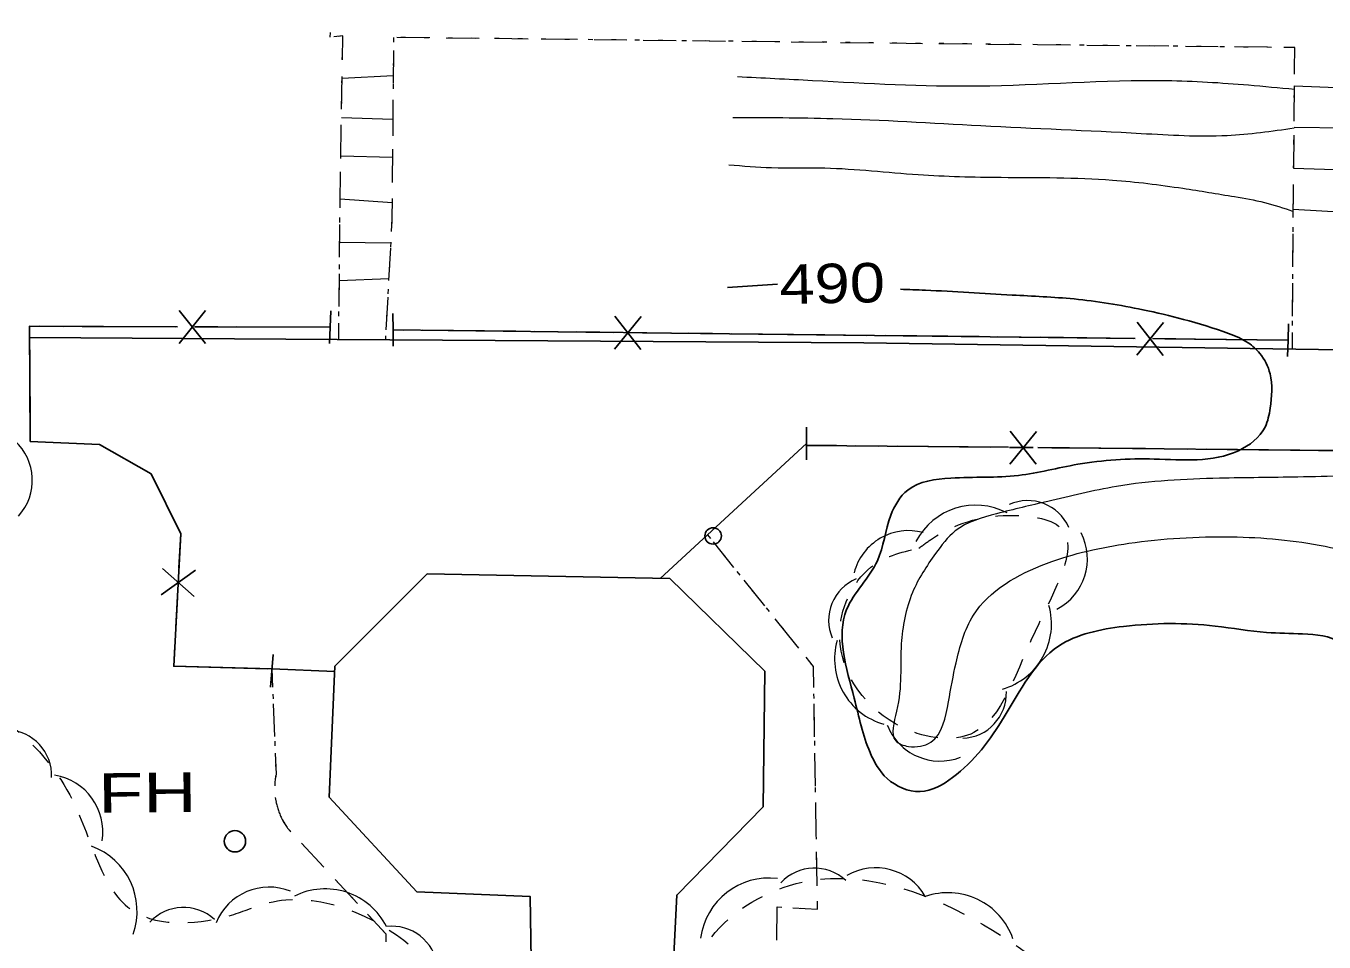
# Model space of a CAD drawing. Extents: x 2362213 to 2366494, y 6968794 to 6978110.
# Drawn here: x 2363996.3 to 2364154.4, y 6972258.7 to 6972370.1 of the extents above; entities that cross this region are included whole.
import ezdxf
from ezdxf.enums import TextEntityAlignment as Align

# ---------------------------------------------------------------- set-up
doc = ezdxf.new("R2010")
doc.units = 0
doc.header["$LTSCALE"] = 1.9
for name, pattern in [('DOTTED', [1.5, 0.3, -1.2]), ('LONG_DASH_SHORT_DASH', [9.9, 6, -1.2, 1.5, -1.2]), ('SHORT_DASHED', [2.7, 1.5, -1.2])]:
    doc.linetypes.add(name, pattern=pattern)
for name, color, linetype, lineweight in [('11', 7, 'Continuous', 25), ('13', 7, 'Continuous', 13), ('17', 7, 'Continuous', 25), ('2', 7, 'Continuous', 25), ('20', 7, 'Continuous', 25), ('29', 7, 'Continuous', 13), ('31', 7, 'Continuous', 25), ('35', 7, 'Continuous', 13), ('9', 7, 'Continuous', 13)]:
    doc.layers.add(name, color=color, linetype=linetype, lineweight=lineweight)

msp = doc.modelspace()

# ---------------------------------------------------------------- linework, layer by layer
at = {"layer": '11'}
msp.add_lwpolyline([(2364091.407, 6972317.335), (2364091.408, 6972319.335), (2364091.409, 6972321.335)], dxfattribs=at)
msp.add_lwpolyline([(2364074.764, 6972302.896), (2364045.218, 6972303.454), (2364033.944, 6972292.236), (2364033.275, 6972276.309), (2364043.956, 6972264.77), (2364057.762, 6972264.192), (2364057.979, 6972248.753), (2364046.682, 6972237.915), (2364046.542, 6972222.143), (2364057.564, 6972210.417), (2364087.81, 6972209.945), (2364099.265, 6972221.125), (2364099.234, 6972237.005), (2364087.978, 6972248.949), (2364074.817, 6972249.053), (2364075.601, 6972264.382), (2364086.129, 6972275.142), (2364086.302, 6972291.645)], close=True, dxfattribs=at)
at = {"layer": '13'}
for p, q in [((2364045.516, 6972368.681), (2364041.516, 6972368.733)), ((2364051.517, 6972368.618), (2364047.517, 6972368.66)), ((2364057.518, 6972368.545), (2364053.517, 6972368.597)), ((2364063.519, 6972368.472), (2364059.519, 6972368.524)), ((2364069.52, 6972368.399), (2364065.52, 6972368.451)), ((2364075.521, 6972368.337), (2364071.52, 6972368.379)), ((2364081.522, 6972368.264), (2364077.521, 6972368.316)), ((2364087.523, 6972368.191), (2364083.522, 6972368.243)), ((2364093.524, 6972368.118), (2364089.523, 6972368.17)), ((2364099.526, 6972368.055), (2364095.524, 6972368.097)), ((2364105.526, 6972367.982), (2364101.525, 6972368.034)), ((2364041.091, 6972367.149), (2364041.059, 6972363.147)), ((2364111.527, 6972367.919), (2364107.526, 6972367.961)), ((2364117.528, 6972367.857), (2364113.527, 6972367.898)), ((2364123.528, 6972367.794), (2364119.528, 6972367.836)), ((2364129.529, 6972367.731), (2364125.529, 6972367.773)), ((2364135.53, 6972367.668), (2364131.53, 6972367.71)), ((2364141.531, 6972367.605), (2364137.53, 6972367.647)), ((2364147.532, 6972367.542), (2364143.532, 6972367.584)), ((2364034.779, 6972359.997), (2364034.841, 6972363.998)), ((2364150.785, 6972358.832), (2364150.817, 6972362.832)), ((2364041.038, 6972361.147), (2364041.006, 6972357.146)), ((2364034.686, 6972353.996), (2364034.748, 6972357.997)), ((2364150.722, 6972352.831), (2364150.764, 6972356.832)), ((2364040.985, 6972355.146), (2364040.953, 6972351.146)), ((2364034.53, 6972341.994), (2364034.572, 6972345.996)), ((2364150.626, 6972340.83), (2364150.658, 6972344.831)), ((2364040.719, 6972343.143), (2364040.507, 6972339.151)), ((2364034.467, 6972335.993), (2364034.509, 6972339.994)), ((2364150.584, 6972334.829), (2364150.615, 6972338.829)), ((2364040.396, 6972337.15), (2364040.184, 6972333.158)), ((2364034.425, 6972331.993), (2364034.446, 6972333.993)), ((2364150.562, 6972330.828), (2364150.573, 6972332.829)), ((2364082.562, 6972304.24), (2364080.062, 6972307.356)), ((2364086.326, 6972299.565), (2364083.817, 6972302.683)), ((2364090.091, 6972294.891), (2364087.581, 6972298.007)), ((2364026.289, 6972291.663), (2364026.368, 6972289.664)), ((2364026.447, 6972287.665), (2364026.615, 6972283.666)), ((2364092.388, 6972283.652), (2364092.32, 6972287.652)), ((2364092.495, 6972277.653), (2364092.427, 6972281.653)), ((2364092.592, 6972271.654), (2364092.524, 6972275.653)), ((2364029.909, 6972270.687), (2364032.637, 6972267.763)), ((2364092.69, 6972265.654), (2364092.622, 6972269.654)), ((2364034.001, 6972266.296), (2364036.729, 6972263.361)), ((2364087.794, 6972258.898), (2364087.806, 6972262.898))]:
    msp.add_line(p, q, dxfattribs=at)
at = {"layer": '13', "linetype": 'DOTTED'}
msp.add_line((2364026.289, 6972291.663), (2364026.799, 6972279.079), dxfattribs=at)
for points in [[(2364034.425, 6972331.993), (2364034.604, 6972348.976), (2364034.914, 6972368.92), (2364033.405, 6972368.776), (2364033.721, 6972377.548)], [(2364150.562, 6972330.828), (2364150.689, 6972350.022), (2364150.862, 6972367.504), (2364041.106, 6972368.739), (2364040.916, 6972346.666), (2364040.116, 6972331.957)], [(2364104.942, 6972207.718), (2364100.511, 6972213.097), (2364104.463, 6972217.084), (2364106.348, 6972220.702), (2364106.73, 6972236.257), (2364104.796, 6972241.909), (2364087.792, 6972253.867), (2364087.805, 6972262.958), (2364092.738, 6972262.655), (2364092.247, 6972292.211), (2364079.354, 6972308.239)], [(2364028.211, 6972272.511), (2364040.164, 6972259.664), (2364039.65, 6972226.528)]]:
    msp.add_lwpolyline(points, dxfattribs=at)
at = {"layer": '13'}
for points in [[(2364034.871, 6972365.998), (2364034.914, 6972368.92), (2364033.835, 6972368.82)], [(2364150.838, 6972364.833), (2364150.862, 6972367.504), (2364149.532, 6972367.521)], [(2364034.593, 6972347.996), (2364034.604, 6972348.976), (2364034.655, 6972351.996)], [(2364150.669, 6972346.831), (2364150.689, 6972350.022), (2364150.701, 6972350.832)], [(2364040.932, 6972349.146), (2364040.916, 6972346.666), (2364040.83, 6972345.145)], [(2364092.291, 6972289.652), (2364092.247, 6972292.211), (2364091.346, 6972293.333)], [(2364026.694, 6972281.667), (2364026.799, 6972279.079), (2364026.77, 6972278.938), (2364026.741, 6972278.798), (2364026.723, 6972278.648), (2364026.704, 6972278.508), (2364026.686, 6972278.367), (2364026.667, 6972278.216), (2364026.648, 6972278.076), (2364026.64, 6972277.936), (2364026.631, 6972277.786), (2364026.632, 6972277.686)], [(2364026.791, 6972275.697), (2364026.812, 6972275.628), (2364026.843, 6972275.488), (2364026.884, 6972275.348), (2364026.916, 6972275.209), (2364026.957, 6972275.069), (2364026.998, 6972274.929), (2364027.04, 6972274.79), (2364027.091, 6972274.66), (2364027.132, 6972274.521), (2364027.184, 6972274.381), (2364027.245, 6972274.252), (2364027.296, 6972274.112), (2364027.357, 6972273.983), (2364027.419, 6972273.853), (2364027.48, 6972273.724), (2364027.541, 6972273.594), (2364027.612, 6972273.465), (2364027.684, 6972273.336), (2364027.755, 6972273.216), (2364027.826, 6972273.087), (2364027.907, 6972272.968), (2364027.978, 6972272.839), (2364028.059, 6972272.719), (2364028.141, 6972272.6), (2364028.211, 6972272.511), (2364028.545, 6972272.154)], [(2364089.746, 6972262.836), (2364092.738, 6972262.655), (2364092.719, 6972263.655)], [(2364038.093, 6972261.894), (2364040.164, 6972259.664), (2364040.153, 6972258.704)]]:
    msp.add_lwpolyline(points, dxfattribs=at)
at = {"layer": '13', "lineweight": 25}
msp.add_circle((2364080.025, 6972308.086), 1, dxfattribs=at)
at = {"layer": '13', "linetype": 'DOTTED'}
msp.add_arc((2364034.915, 6972277.388), 8.291, 168.24089, 216.03626, dxfattribs=at)
at = {"layer": '17'}
for p, q in [((2364018.201, 6972335.508), (2364014.989, 6972331.518)), ((2364015.001, 6972335.518), (2364018.189, 6972331.508)), ((2364033.391, 6972333.493), (2364018.39, 6972333.53)), ((2364071.27, 6972334.784), (2364068.028, 6972330.813)), ((2364068.07, 6972334.813), (2364071.218, 6972330.783)), ((2364134.86, 6972334.049), (2364131.618, 6972330.088)), ((2364131.67, 6972334.089), (2364134.818, 6972330.049)), ((2364067.839, 6972332.851), (2364041.045, 6972333.156)), ((2364131.438, 6972332.126), (2364071.439, 6972332.805)), ((2364150.041, 6972331.904), (2364135.039, 6972332.081)), ((2364119.406, 6972320.801), (2364116.163, 6972316.83)), ((2364116.205, 6972320.831), (2364119.364, 6972316.801)), ((2364115.974, 6972318.869), (2364091.411, 6972319.105)), ((2364179.573, 6972318.244), (2364119.574, 6972318.833)), ((2364012.82, 6972300.926), (2364016.982, 6972303.905)), ((2364012.99, 6972304.117), (2364016.812, 6972300.714))]:
    msp.add_line(p, q, dxfattribs=at)
at = {"layer": '17', "linetype": 'LONG_DASH_SHORT_DASH'}
msp.add_line((2364150.041, 6972331.904), (2364041.045, 6972333.156), dxfattribs=at)
for points in [[(2364033.391, 6972333.493), (2363996.758, 6972333.594), (2363996.862, 6972319.584), (2364005.316, 6972319.215), (2364011.58, 6972315.654), (2364015.19, 6972308.338), (2364014.333, 6972292.22), (2364026.307, 6972291.904)], [(2364211.497, 6972263.486), (2364211.989, 6972312.613), (2364189.085, 6972318.155), (2364091.411, 6972319.105)]]:
    msp.add_lwpolyline(points, dxfattribs=at)
at = {"layer": '17'}
for points in [[(2364014.79, 6972333.536), (2363996.758, 6972333.594), (2363996.862, 6972319.584), (2364005.316, 6972319.215), (2364011.58, 6972315.654), (2364015.19, 6972308.338), (2364014.969, 6972304.216)], [(2364014.783, 6972300.625), (2364014.333, 6972292.22), (2364026.307, 6972291.904)]]:
    msp.add_lwpolyline(points, dxfattribs=at)
at = {"layer": '2'}
for p, q in [((2364091.408, 6972319.335), (2364073.564, 6972302.915)), ((2364026.307, 6972291.904), (2364033.92, 6972291.576))]:
    msp.add_line(p, q, dxfattribs=at)
for points in [[(2364212.614, 6972335.16), (2364189.088, 6972330.415), (2364156.503, 6972330.745), (2364098.372, 6972331.592), (2364034.235, 6972331.991), (2363996.771, 6972332.244)], [(2364033.472, 6972335.494), (2364033.391, 6972333.493), (2364033.31, 6972331.492)], [(2364041.074, 6972331.156), (2364041.045, 6972333.156), (2364041.015, 6972335.156)], [(2364150.092, 6972333.904), (2364150.041, 6972331.904), (2364149.99, 6972329.903)], [(2364026.46, 6972293.655), (2364026.289, 6972291.663), (2364026.118, 6972289.672)]]:
    msp.add_lwpolyline(points, dxfattribs=at)
at = {"layer": '20'}
msp.add_circle((2364021.786, 6972270.93), 1.3, dxfattribs=at)
at = {"layer": '29'}
for centre, radius, start, end in [((2363990.621, 6972314.861), 6.496, 317.82148, 47.82148), ((2364112.012, 6972303.577), 8.248, 62.33333, 152.33333), ((2364118.32, 6972306.883), 5.495, 24.03678, 114.03678), ((2364103.839, 6972301.856), 6.876, 75.18483, 165.18483), ((2364118.727, 6972305.291), 6.876, 297.46231, 27.46231), ((2364099.589, 6972297.813), 5.495, 112.98541, 202.98541), ((2364112.982, 6972297.375), 8.248, 285.92314, 15.92314), ((2364103.059, 6972293.112), 8.248, 164.17223, 254.17223), ((2364110.248, 6972288.972), 5.495, 271.75033, 1.75033), ((2363993.904, 6972278.917), 5.569, 357.76049, 87.76049), ((2364107.638, 6972287.565), 6.876, 201.2658, 291.2658), ((2363998.735, 6972272.084), 6.969, 350.89891, 80.89891), ((2364001.515, 6972262.451), 8.359, 340.254, 70.254), ((2364092.362, 6972262.082), 5.582, 46.95733, 136.95733), ((2364099.821, 6972260.721), 6.984, 30.13221, 120.13221), ((2364025.945, 6972258.384), 6.969, 67.9202, 157.9202), ((2364086.814, 6972258.078), 8.377, 82.82142, 172.82142), ((2364032.788, 6972256.784), 8.359, 26.72281, 116.72281), ((2364108.623, 6972256.301), 8.377, 19.28758, 109.28758), ((2364015.534, 6972257.313), 5.569, 47.48666, 137.48666), ((2364040.928, 6972255.024), 5.569, 6.90129, 96.90129)]:
    msp.add_arc(centre, radius, start, end, dxfattribs=at)
at = {"layer": '29', "linetype": 'SHORT_DASHED'}
for points in [[(2364105.08, 6972306.604), (2364106.719, 6972307.76), (2364116.033, 6972310.589), (2364122.308, 6972309.118), (2364119.227, 6972296.459), (2364110.609, 6972283.706), (2364102.234, 6972285.226), (2364095.445, 6972296.612), (2364099.7, 6972304.623), (2364105.949, 6972306.743)], [(2364002.5, 6972032.034), (2363981.216, 6972031.281), (2363965.113, 6972033.558), (2363944.353, 6972058.733), (2363938.042, 6972103.955), (2363937.106, 6972153.928), (2363939.297, 6972178.99), (2363948.28, 6972195.626), (2363955.069, 6972199.951), (2363959.924, 6972225.708), (2363951.126, 6972253.846), (2363948.395, 6972267.54), (2363949.343, 6972293.971), (2363967.597, 6972294.775), (2363985.559, 6972290.335), (2364002.018, 6972275.921), (2364009.456, 6972262.422), (2364021.661, 6972262.038), (2364025.937, 6972263.469), (2364042.362, 6972258.885), (2364049.893, 6972249.316), (2364049.696, 6972227.003), (2364040.844, 6972210.288), (2364042.236, 6972190.211), (2364050.399, 6972166.826), (2364050.37, 6972138.336), (2364039.719, 6972118.392), (2364026.745, 6972108.349), (2364021.559, 6972100.549), (2364016.664, 6972074.761), (2364015.764, 6972053.761), (2364011.499, 6972039.551), (2364002.406, 6972032.463)], [(2364073.753, 6972229.492), (2364074.958, 6972240.484), (2364079.78, 6972259.201), (2364090.957, 6972265.968), (2364111.841, 6972261.407), (2364127.953, 6972249.69), (2364140.932, 6972237.293), (2364150.158, 6972217.769), (2364149.676, 6972192.814), (2364127.259, 6972175.53), (2364100.53, 6972178.585), (2364079.39, 6972180.474), (2364064.989, 6972186.857), (2364056.757, 6972205.86), (2364062.954, 6972218.879), (2364072.992, 6972229.555)]]:
    msp.add_spline(points, degree=3, dxfattribs=at)
at = {"layer": '31'}
msp.add_line((2364081.787, 6972338.314), (2364087.874, 6972338.712), dxfattribs=at)
msp.add_spline([(2364102.84, 6972338.094), (2364105.871, 6972337.983), (2364116.438, 6972337.394), (2364123.972, 6972336.916), (2364132.355, 6972335.605), (2364137.317, 6972334.433), (2364142.793, 6972332.715), (2364145.185, 6972331.577), (2364146.596, 6972330.301), (2364147.85, 6972327.813), (2364147.86, 6972323.633), (2364147.242, 6972321.326), (2364144, 6972318.455), (2364133.748, 6972317.438), (2364124.424, 6972316.799), (2364117.197, 6972315.45), (2364108.969, 6972315.122), (2364103.723, 6972313.652), (2364101.652, 6972310.602), (2364100.036, 6972305.066), (2364096.281, 6972299.12), (2364097.204, 6972288.348), (2364099.138, 6972281.727), (2364101.207, 6972278.577), (2364105.222, 6972276.994), (2364109.186, 6972278.683), (2364115.476, 6972286.092), (2364122.086, 6972294.676), (2364130.012, 6972297.071), (2364141.162, 6972297.117), (2364147.43, 6972296.347), (2364151.812, 6972296.169), (2364156.442, 6972295.083), (2364158.831, 6972292.125), (2364160.256, 6972289.459), (2364160.767, 6972284.074), (2364162.945, 6972279.085), (2364165.154, 6972269.865), (2364164.2, 6972261.715), (2364164.157, 6972253.674), (2364169.037, 6972243.28), (2364175.717, 6972237.964), (2364181.292, 6972235.407), (2364187.732, 6972229.158), (2364190.016, 6972223.559), (2364193.561, 6972213.603), (2364199.445, 6972206.788), (2364202.052, 6972198.673), (2364199.336, 6972190.977), (2364195.351, 6972186.188), (2364190.01, 6972183.197), (2364183.612, 6972181.786), (2364178.059, 6972182.144), (2364171.614, 6972185.782), (2364164.38, 6972189.343), (2364158.538, 6972190.548), (2364154.057, 6972191.705), (2364148.58, 6972192.373), (2364140.562, 6972192.107), (2364135.613, 6972191.95), (2364130.237, 6972192.549), (2364122.358, 6972191.474), (2364114.296, 6972188.446), (2364108.6, 6972185.882)], degree=3, dxfattribs=at)
at = {"layer": '35'}
for points in [[(2364150.811, 6972362.402), (2364145.217, 6972362.919), (2364135.24, 6972363.454), (2364112.265, 6972362.805), (2364092.128, 6972363.474), (2364082.983, 6972363.936)], [(2364082.44, 6972359.011), (2364094.622, 6972358.877), (2364112.631, 6972358.019), (2364132.161, 6972357.064), (2364142.604, 6972356.824), (2364150.766, 6972357.722)], [(2364156.982, 6972357.111), (2364163.014, 6972356.878), (2364167.565, 6972355.832), (2364175.992, 6972354.032), (2364185.051, 6972353.078), (2364190.675, 6972351.741), (2364195.111, 6972347.874), (2364197.12, 6972345.913), (2364199.868, 6972344.019), (2364201.142, 6972342.611), (2364203.512, 6972338.413), (2364205.18, 6972336.499), (2364205.619, 6972334.563), (2364205.944, 6972332.916), (2364206.745, 6972328.633), (2364207.416, 6972325.441), (2364207.944, 6972320.364), (2364208.244, 6972317.217), (2364207.15, 6972313.467), (2364204.179, 6972312.438), (2364196.566, 6972312.736), (2364187.127, 6972313.636), (2364174.486, 6972313.656), (2364168.381, 6972313.267), (2364166.166, 6972312.666), (2364165.388, 6972311.479), (2364166.158, 6972308.236), (2364171.608, 6972306.138), (2364177.776, 6972305.306), (2364186.266, 6972303.228), (2364191.265, 6972299.295), (2364194.967, 6972291.66), (2364192.618, 6972284.307), (2364186.443, 6972276.298), (2364184.488, 6972273.659), (2364183.127, 6972267.446), (2364183.072, 6972261.625), (2364185.262, 6972256.356), (2364190.813, 6972252.198), (2364194.778, 6972249.526), (2364200.631, 6972246.091), (2364205.045, 6972236.273), (2364207.432, 6972227.115), (2364209.143, 6972217.511), (2364210.284, 6972206.001), (2364210.991, 6972195.838), (2364210.178, 6972186.71), (2364206.661, 6972178.876), (2364200.562, 6972173.547), (2364193.549, 6972170.691), (2364188.918, 6972169.726), (2364182.15, 6972169.442), (2364173.736, 6972169.782), (2364167.01, 6972170.538), (2364157.223, 6972173.185), (2364150.176, 6972173.918), (2364138.499, 6972174.527), (2364132.401, 6972174.348), (2364126.267, 6972174.71)], [(2364081.925, 6972353.256), (2364087.139, 6972352.906), (2364093.619, 6972352.857), (2364105.007, 6972352.056), (2364115.091, 6972351.722), (2364128.665, 6972351.391), (2364137.225, 6972350.383), (2364143.526, 6972349.373), (2364147.152, 6972348.668), (2364150.672, 6972347.571)], [(2364156.995, 6972347.331), (2364160.667, 6972346.106), (2364162.586, 6972345.165), (2364166.25, 6972342.718), (2364169.314, 6972340.257), (2364171.614, 6972335.889), (2364175.471, 6972332.106), (2364177.736, 6972330.517), (2364178.425, 6972328.474), (2364178.831, 6972324.698), (2364178.516, 6972322.134), (2364174.454, 6972318.045), (2364169.799, 6972316.591), (2364162.666, 6972315.733), (2364151.22, 6972315.244), (2364141.671, 6972315.103), (2364129.13, 6972314.104), (2364120.767, 6972312.284), (2364114.541, 6972310.785), (2364109.511, 6972308.687), (2364107.107, 6972305.934), (2364104.302, 6972301.198), (2364102.941, 6972294.953), (2364102.369, 6972286.758), (2364102.263, 6972283.166), (2364103.8, 6972282.481), (2364106.535, 6972282.997), (2364108.679, 6972287.898), (2364109.604, 6972292.627), (2364111.718, 6972298.427), (2364120.639, 6972304.732), (2364130.666, 6972307.188), (2364143.13, 6972307.977), (2364154.54, 6972306.825), (2364165.245, 6972304.408), (2364176.934, 6972302.379), (2364182.801, 6972298.454), (2364186.429, 6972292.418), (2364184.871, 6972284.823), (2364181.825, 6972279.165), (2364177.519, 6972272.473), (2364176.651, 6972269.094), (2364174.659, 6972262.935), (2364174.777, 6972258.966), (2364178.234, 6972252.978), (2364185.185, 6972245.554), (2364192.026, 6972237.169), (2364195.584, 6972233.093), (2364199.562, 6972222.83), (2364202.977, 6972213.962), (2364204.933, 6972208.031), (2364206.356, 6972193.034), (2364205.191, 6972184.092), (2364201.736, 6972179.389), (2364195.025, 6972175.265), (2364188.046, 6972174.148), (2364179.363, 6972176.486), (2364173.338, 6972180.069), (2364163.553, 6972181.645), (2364154.897, 6972182.193), (2364148.176, 6972182.289), (2364140.445, 6972182.315), (2364130.385, 6972182.27), (2364122.188, 6972182.072), (2364114.275, 6972180.156), (2364105.164, 6972177.009), (2364085.937, 6972172.446)]]:
    msp.add_spline(points, degree=3, dxfattribs=at)
at = {"layer": '9'}
for p, q in [((2364041.07, 6972364.087), (2364034.833, 6972363.728)), ((2364156.99, 6972362.551), (2364150.817, 6972362.792)), ((2364041.021, 6972358.757), (2364034.759, 6972358.957)), ((2364156.986, 6972357.721), (2364150.765, 6972357.782)), ((2364040.985, 6972354.136), (2364034.683, 6972354.296)), ((2364156.975, 6972352.571), (2364150.713, 6972352.791)), ((2364040.937, 6972348.636), (2364034.603, 6972349.046)), ((2364156.954, 6972347.421), (2364150.67, 6972347.821)), ((2364034.553, 6972343.824), (2364040.754, 6972343.753)), ((2364040.515, 6972339.371), (2364034.497, 6972339.134))]:
    msp.add_line(p, q, dxfattribs=at)

# ---------------------------------------------------------------- texts
at = {"layer": '20', "width": 1.4}
msp.add_text('  FH', height=4.8, rotation=0.546, dxfattribs=at).set_placement((2364000.163, 6972274.354))
at = {"layer": '31', "width": 1.2}
msp.add_text(' 490 ', height=4.8, rotation=1.074, dxfattribs=at).set_placement((2364094.563, 6972336.415), align=Align.CENTER)

doc.saveas('drawing.dxf')
